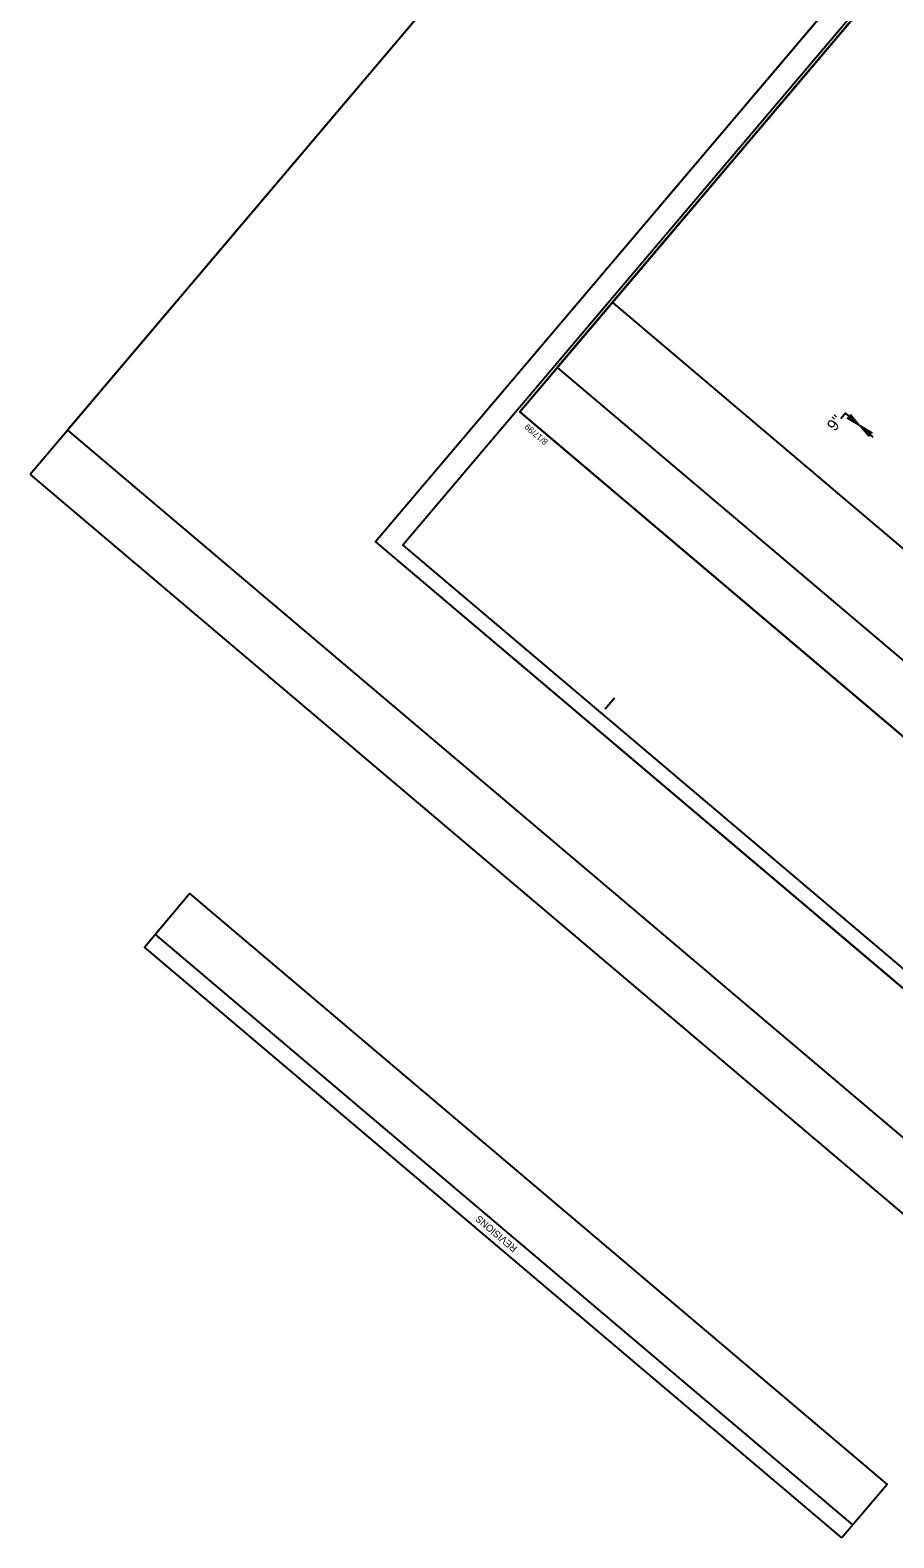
# Model space of a CAD drawing. Extents: x 1763138 to 1764249, y 424045 to 425159.
# Drawn here: x 1763138 to 1763511, y 424045 to 424697 of the extents above; entities that cross this region are included whole.
import ezdxf

# ---------------------------------------------------------------- set-up
doc = ezdxf.new("R2010")
doc.units = 0
for name, color, linetype in [('Default', 7, 'Continuous'), ('Old_Level_11', 7, 'Continuous'), ('Prop Dimension Text', 7, 'Continuous'), ('Sheet Block Revision CELL', 7, 'Continuous'), ('Sheet Clip Boundary CELL', 7, 'Continuous'), ('Sheet Cutting Line CELL', 7, 'Continuous'), ('Sheet Data Field CELL', 7, 'Continuous'), ('Sheet Plan CELL', 7, 'Continuous'), ('Sheet Plan Layout CELL', 7, 'Continuous'), ('Sheet Plot Border Inside CELL', 7, 'Continuous'), ('Sheet Sticker Exception Certification CELL', 7, 'Continuous'), ('Sheet Title CELL', 7, 'Continuous')]:
    doc.layers.add(name, color=color, linetype=linetype)

# ---------------------------------------------------------------- blocks, each defined once
blk = doc.blocks.new('Terminator')
at = {"layer": 'Old_Level_11'}
blk.add_lwpolyline([(-9, 1.55), (0, 0), (-9.05, -1.6), (-7.9, 0)], close=True, dxfattribs=at)

msp = doc.modelspace()

# ---------------------------------------------------------------- linework, layer by layer
at = {"layer": 'Old_Level_11'}
msp.add_lwpolyline([(1763500.09, 424521.66), (1763496.44, 424526.1), (1763501.41, 424523.14), (1763500.2, 424522.85)], close=True, dxfattribs=at)
at = {"layer": 'Sheet Block Revision CELL'}
for points in [[(1763765.97, 424212), (1764218.44, 424746.11), (1763898.55, 425017.11), (1763837.38, 424944.91), (1763756.7, 425013.26), (1763365.39, 424551.35)], [(1763554.26, 424184.86), (1764006.73, 424718.97), (1763686.84, 424989.97), (1763625.67, 424917.77), (1763544.99, 424986.12), (1763153.68, 424524.22)]]:
    msp.add_lwpolyline(points, close=True, dxfattribs=at)
at = {"layer": 'Sheet Clip Boundary CELL'}
for p, q in [((1763830.94, 425118.29), (1763286.84, 424476.03)), ((1763286.84, 424476.03), (1763704.59, 424122.13))]:
    msp.add_line(p, q, dxfattribs=at)
at = {"layer": 'Sheet Cutting Line CELL'}
for points in [[(1763349.23, 424532.26), (1763749.81, 424192.92), (1764234.6, 424765.18), (1763914.7, 425036.18), (1763837.38, 424944.91), (1763756.7, 425013.26)], [(1763137.52, 424505.12), (1763538.1, 424165.79), (1764022.89, 424738.04), (1763702.99, 425009.04), (1763625.67, 424917.77), (1763544.99, 424986.12)]]:
    msp.add_lwpolyline(points, close=True, dxfattribs=at)
at = {"layer": 'Sheet Data Field CELL'}
for p, q in [((1763349.23, 424532.28), (1763349.23, 424532.28)), ((1763386.13, 424403.7), (1763390.16, 424408.49))]:
    msp.add_line(p, q, dxfattribs=at)
for points in [[(1763834.03, 425104.55), (1763349.23, 424532.28), (1763749.81, 424192.92), (1764234.6, 424765.18)], [(1763749.81, 424192.92), (1763349.23, 424532.26), (1763769.36, 425028.22), (1763826.62, 424979.73), (1763891.27, 425056.04), (1764234.6, 424765.18)]]:
    msp.add_lwpolyline(points, close=True, dxfattribs=at)
at = {"layer": 'Sheet Plan CELL'}
msp.add_line((1763493.22, 424050.79), (1763191.58, 424306.31), dxfattribs=at)
msp.add_lwpolyline([(1763488.52, 424045.23), (1763186.89, 424300.76), (1763206.44, 424323.87), (1763508.08, 424068.33)], close=True, dxfattribs=at)
at = {"layer": 'Sheet Plan Layout CELL'}
msp.add_lwpolyline([(1763701.16, 424133.55), (1764239.59, 424769.14), (1763837.12, 425110.11), (1763298.67, 424474.52)], close=True, dxfattribs=at)
at = {"layer": 'Sheet Plot Border Inside CELL'}
msp.add_lwpolyline([(1763704.59, 424122.13), (1764248.69, 424764.39), (1763830.94, 425118.29), (1763286.84, 424476.03)], close=True, dxfattribs=at)
at = {"layer": 'Sheet Sticker Exception Certification CELL'}
msp.add_lwpolyline([(1763589.54, 424409.85), (1763969.1, 424857.88), (1763768.81, 425027.56), (1763389.25, 424579.52)], close=True, dxfattribs=at)
at = {"layer": 'Sheet Title CELL'}
msp.add_lwpolyline([(1763502, 424521.3), (1763489.98, 424531.67), (1763487.96, 424529.15)], dxfattribs=at)

# ---------------------------------------------------------------- block references
at = {"layer": 'Default', "xscale": 0.6300000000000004, "yscale": 0.6299999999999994, "rotation": -40.78193183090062}
msp.add_blockref('Terminator', (1763495.87, 424526.59), dxfattribs=at)

# ---------------------------------------------------------------- texts
at = {"layer": 'Prop Dimension Text'}
msp.add_text('9"', height=5, rotation=51.24637, dxfattribs=at).set_placement((1763485.44, 424523.5))
at = {"layer": 'Sheet Data Field CELL'}
msp.add_text('8/17/99', height=2.625, rotation=139.73011, dxfattribs=at).set_placement((1763361.62, 424519.66))
at = {"layer": 'Sheet Plan CELL'}
msp.add_text('REVISIONS', height=3, rotation=139.7301, dxfattribs=at).set_placement((1763348.4, 424170.81))

doc.saveas('drawing.dxf')
